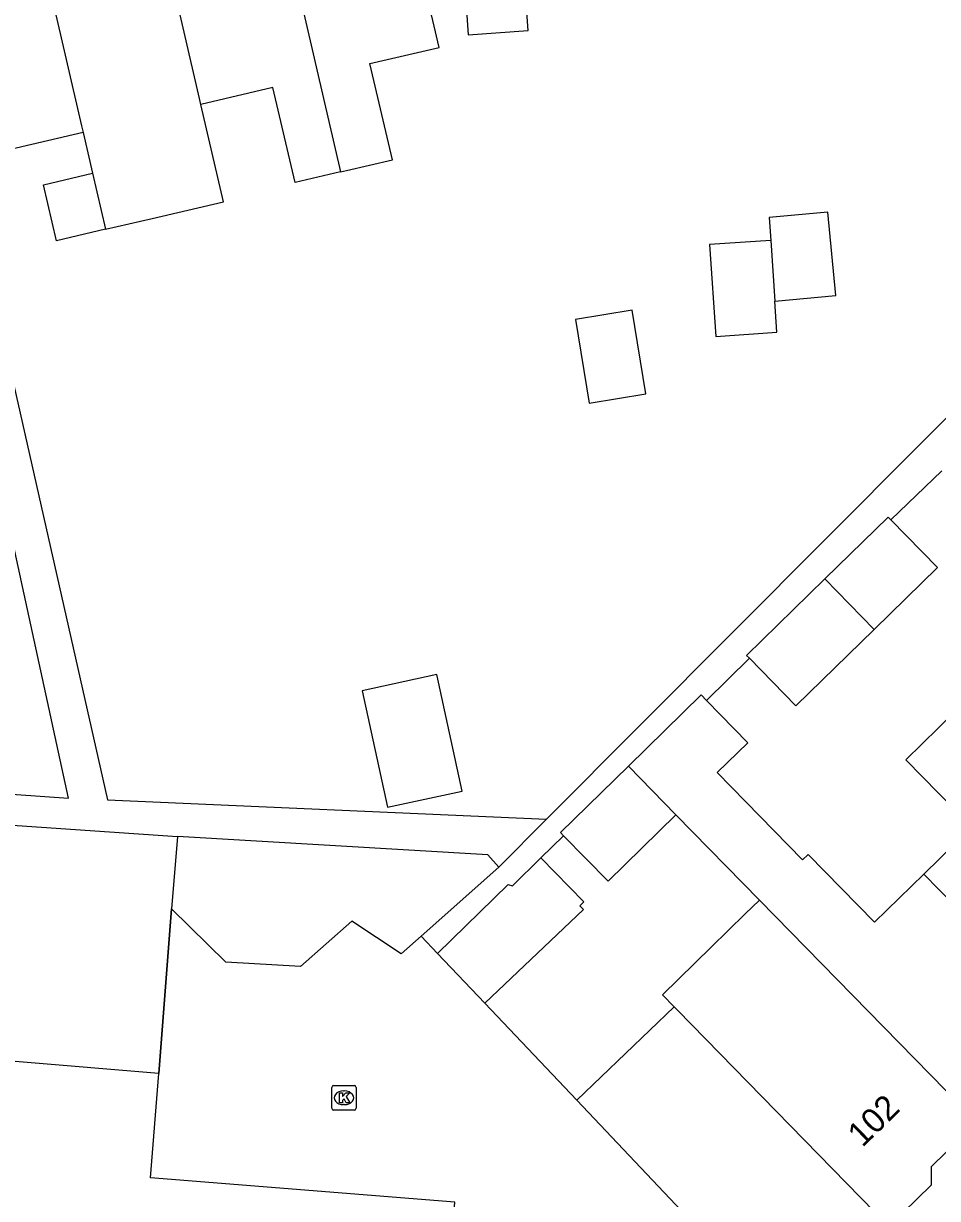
# Model space of a CAD drawing. Extents: x 160861 to 161308, y 384024 to 384878.
# Drawn here: x 161006.07 to 161043.45, y 384645.25 to 384693.28 of the extents above; entities that cross this region are included whole.
import ezdxf

# ---------------------------------------------------------------- set-up
doc = ezdxf.new("R2010")
doc.units = 0
for name, color, linetype in [('IMGEO_Hek', 7, 'Continuous'), ('IMGEO_Kolk', 7, 'Continuous'), ('IMGEO_Muur', 7, 'Continuous'), ('IMGEO_Pand', 7, 'Continuous'), ('IMGEO_Pand_nummerreeks', 7, 'Continuous'), ('IMGEO_Rijbaan_lokaal_open', 7, 'Continuous'), ('IMGEO_Voetpad_open', 7, 'Continuous')]:
    doc.layers.add(name, color=color, linetype=linetype)

msp = doc.modelspace()

# ---------------------------------------------------------------- linework, layer by layer
at = {"layer": 'IMGEO_Hek'}
for points in [[(161011.607, 384650.352), (161012.121, 384657.087)], [(161022.327, 384655.974), (161023.003, 384655.261)]]:
    msp.add_lwpolyline(points, dxfattribs=at)
at = {"layer": 'IMGEO_Kolk'}
for p, q in [((161018.672, 384648.937), (161018.672, 384649.789)), ((161018.747, 384649.863), (161019.599, 384649.863)), ((161019.673, 384649.789), (161019.673, 384648.937)), ((161019.16, 384649.643), (161019.185, 384649.643)), ((161019.599, 384648.863), (161018.747, 384648.863)), ((161019.183, 384649.083), (161019.158, 384649.083))]:
    msp.add_line(p, q, dxfattribs=at)
for points in [[(161018.672, 384648.937), (161018.672, 384649.789)], [(161018.747, 384649.863), (161019.599, 384649.863)], [(161019.673, 384649.789), (161019.673, 384648.937)], [(161018.993, 384649.563), (161019.116, 384649.563), (161019.116, 384649.412), (161019.246, 384649.563), (161019.41, 384649.563), (161019.264, 384649.412), (161019.417, 384649.163), (161019.265, 384649.163), (161019.18, 384649.327), (161019.116, 384649.26), (161019.116, 384649.163), (161018.993, 384649.163), (161018.993, 384649.563)], [(161019.599, 384648.863), (161018.747, 384648.863)]]:
    msp.add_lwpolyline(points, dxfattribs=at)
for centre, start, end in [((161018.749, 384649.787), 91.552, 178.448), ((161018.749, 384649.787), 91.552, 178.448), ((161019.597, 384649.787), 1.552, 88.448), ((161019.597, 384649.787), 1.552, 88.448), ((161018.749, 384648.939), 181.552, 268.448), ((161018.749, 384648.939), 181.552, 268.448), ((161019.597, 384648.939), 271.552, 358.448), ((161019.597, 384648.939), 271.552, 358.448)]:
    msp.add_arc(centre, 0.0765, start, end, dxfattribs=at)
for centre, major_axis, ratio, start_param, end_param in [((161019.159, 384649.363), (-0.387, 0.002), 0.722429, 4.712389, 7.853982), ((161019.184, 384649.363), (-0.39, 0.002), 0.717154, 1.570796, 4.712389)]:
    msp.add_ellipse(centre, major_axis=major_axis, ratio=ratio, start_param=start_param, end_param=end_param, dxfattribs=at)
at = {"layer": 'IMGEO_Muur'}
msp.add_lwpolyline([(161024.93, 384653.23), (161028.69, 384649.268)], dxfattribs=at)
at = {"layer": 'IMGEO_Pand'}
for points in [[(161019.037, 384687.212), (161019.271, 384687.267), (161021.153, 384687.708), (161020.234, 384691.638), (161023.066, 384692.301), (161022.343, 384695.393), (161021.204, 384700.261), (161016.279, 384699.12)], [(161016.279, 384699.12), (161018.084, 384691.326), (161019.037, 384687.212)], [(161013.321, 384689.966), (161013.265, 384690.21), (161011.46, 384698.004)], [(161006.641, 384696.888), (161008.446, 384689.093), (161008.509, 384688.823)], [(161023.979, 384696.8), (161024.259, 384692.814), (161026.705, 384692.986), (161026.426, 384696.972), (161023.979, 384696.8)], [(161019.037, 384687.212), (161017.177, 384686.777), (161016.27, 384690.656), (161013.321, 384689.966)], [(161009.425, 384684.865), (161011.333, 384685.311), (161014.25, 384685.993), (161013.321, 384689.966)], [(161008.509, 384688.823), (161005.999, 384688.235), (161003.583, 384687.669)], [(161008.509, 384688.823), (161008.894, 384687.157)], [(161009.425, 384684.865), (161007.417, 384684.395), (161006.881, 384686.686), (161008.894, 384687.157)], [(161008.894, 384687.157), (161009.425, 384684.865)], [(161036.79, 384681.925), (161039.288, 384682.159), (161038.967, 384685.567), (161036.561, 384685.34), (161036.623, 384684.41)], [(161036.623, 384684.41), (161034.127, 384684.24), (161034.38, 384680.485), (161036.876, 384680.653), (161036.79, 384681.925)], [(161036.623, 384684.41), (161036.79, 384681.925)], [(161028.641, 384681.181), (161029.197, 384677.76), (161031.511, 384678.136), (161030.955, 384681.557), (161028.641, 384681.181)], [(161038.839, 384670.576), (161041.427, 384673.103), (161041.541, 384672.986)], [(161041.541, 384672.986), (161043.444, 384671.038), (161040.859, 384668.512)], [(161038.839, 384670.576), (161035.637, 384667.448), (161035.754, 384667.328)], [(161040.859, 384668.512), (161038.839, 384670.576)], [(161040.859, 384668.512), (161037.655, 384665.382), (161035.754, 384667.328)], [(161019.923, 384666), (161020.953, 384661.24), (161024.002, 384661.9), (161022.971, 384666.66), (161019.923, 384666)], [(161033.998, 384665.608), (161033.779, 384665.832), (161030.805, 384662.922)], [(161042.888, 384658.505), (161040.875, 384656.536), (161038.16, 384659.312), (161037.93, 384659.087), (161034.44, 384662.655), (161035.691, 384663.879), (161033.998, 384665.608)], [(161042.888, 384658.505), (161044.847, 384660.422), (161042.148, 384663.181), (161044.154, 384665.144)], [(161030.805, 384662.922), (161028.027, 384660.205), (161028.155, 384660.074)], [(161032.749, 384660.935), (161030.805, 384662.922)], [(161028.155, 384660.074), (161029.972, 384658.217), (161032.749, 384660.935)], [(161036.163, 384657.446), (161032.749, 384660.935)], [(161012.363, 384660.051), (161012.121, 384657.087)], [(161025.503, 384658.795), (161025.054, 384659.301), (161012.363, 384660.051)], [(161023.003, 384655.261), (161025.884, 384658.08), (161026.065, 384658.029), (161027.228, 384659.167)], [(161027.228, 384659.167), (161028.98, 384657.376), (161028.815, 384657.214), (161028.966, 384657.06), (161024.93, 384653.23)], [(161025.503, 384658.795), (161022.327, 384655.974)], [(161049.014, 384652.243), (161042.888, 384658.505)], [(161032.68, 384653.079), (161032.2, 384653.569), (161034.191, 384655.517), (161035.583, 384656.879), (161036.163, 384657.446)], [(161036.163, 384657.446), (161045.05, 384648.363)], [(161022.327, 384655.974), (161021.518, 384655.255), (161019.495, 384656.588), (161017.397, 384654.724), (161014.337, 384654.905), (161012.121, 384657.087)], [(161023.003, 384655.261), (161024.93, 384653.23)], [(161011.607, 384650.352), (161000, 384651.318), (160973.59, 384653.518), (160973.559, 384653.621)], [(161028.69, 384649.268), (161032.68, 384653.079)], [(161032.68, 384653.079), (161032.814, 384652.942), (161041.458, 384644.107)], [(161023.199, 384638.753), (161023.706, 384645.1), (161011.266, 384646.094), (161011.607, 384650.352)], [(161028.69, 384649.268), (161033.936, 384643.741), (161037.434, 384640.168)], [(161045.05, 384648.363), (161043.192, 384646.544), (161043.184, 384645.796), (161041.458, 384644.107)]]:
    msp.add_lwpolyline(points, dxfattribs=at)
at = {"layer": 'IMGEO_Rijbaan_lokaal_open'}
for points in [[(161012.121, 384657.087), (161011.607, 384650.352)], [(161022.327, 384655.974), (161023.003, 384655.261)], [(161024.93, 384653.23), (161028.69, 384649.268)]]:
    msp.add_lwpolyline(points, dxfattribs=at)
at = {"layer": 'IMGEO_Voetpad_open'}
for points in [[(161003.583, 384687.669), (161009.497, 384661.544), (161027.455, 384660.754)], [(161050.355, 384683.728), (161027.455, 384660.754)], [(160970.021, 384680.67), (160975.646, 384663.885), (161007.907, 384661.614), (161004.02, 384679.414)], [(160969.466, 384678.232), (160975.017, 384662.612), (161012.363, 384660.051)], [(161043.624, 384674.991), (161041.541, 384672.986)], [(161035.754, 384667.328), (161033.998, 384665.608)], [(161027.455, 384660.754), (161025.503, 384658.795)], [(161028.155, 384660.074), (161027.228, 384659.167)]]:
    msp.add_lwpolyline(points, dxfattribs=at)

# ---------------------------------------------------------------- texts
at = {"layer": 'IMGEO_Pand_nummerreeks'}
msp.add_text('102', height=1, rotation=44.3068, dxfattribs=at).set_placement((161040.37, 384647.306))

doc.saveas('drawing.dxf')
